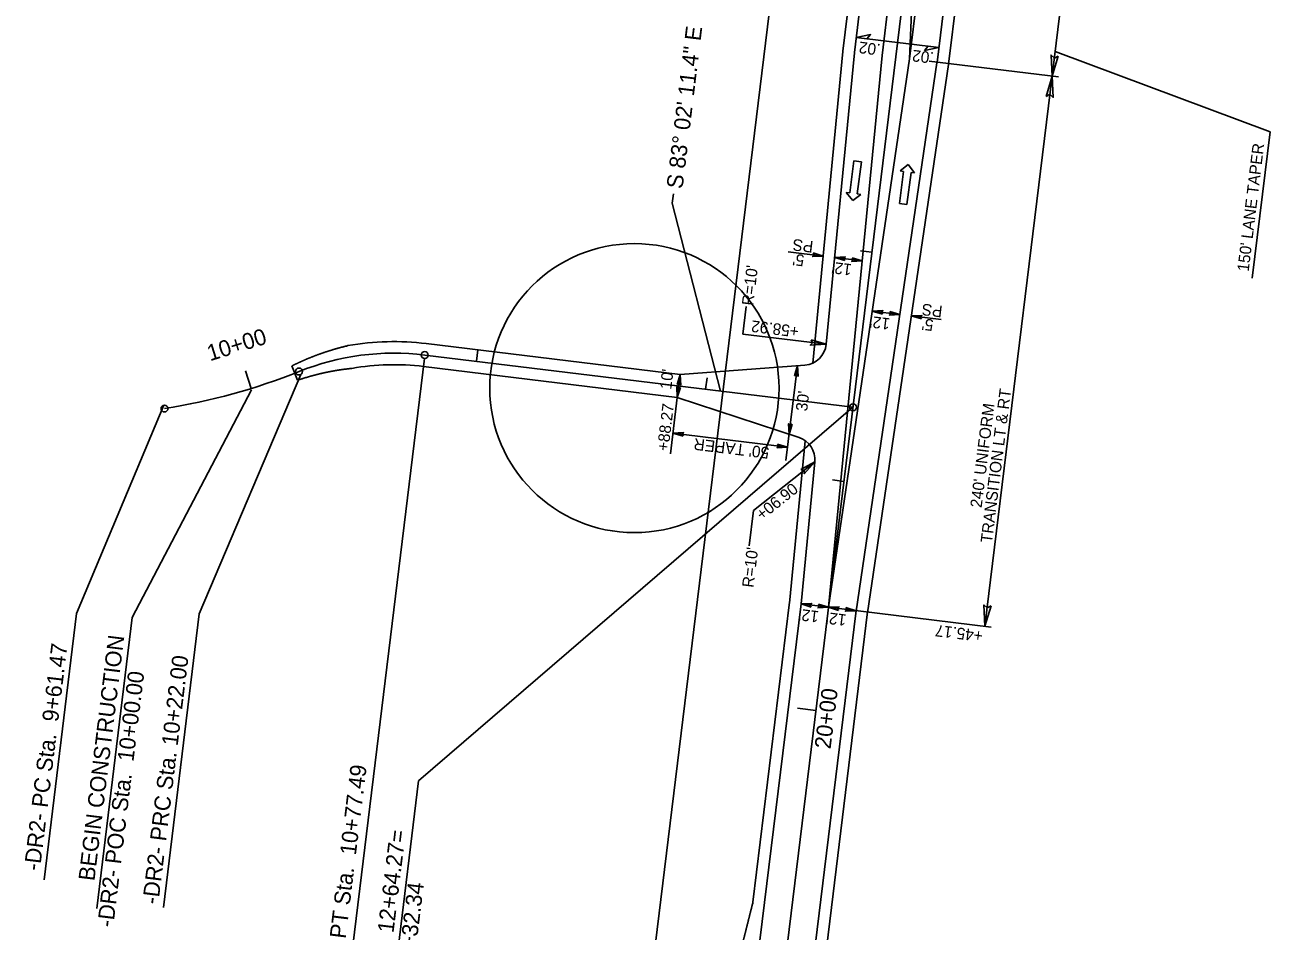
# Model space of a CAD drawing. Extents: x 472216 to 481979, y 489069 to 507339.
# Drawn here: x 480925 to 481464, y 489992 to 490385 of the extents above; entities that cross this region are included whole.
import ezdxf

# ---------------------------------------------------------------- set-up
doc = ezdxf.new("R2010")
doc.units = 0
for name, color, linetype in [('Old_Level_12', 7, 'Continuous'), ('Prop Drainage Structure Drop Inlet Grate 2 Narrow Slots and Sag Grates 840 24 CELL', 7, 'Continuous'), ('Prop Drainage Structure Drop Inlet Grate 2 Wide Slots and Sag Grates 840 22 Label', 7, 'Continuous'), ('Prop Drainage Structure Outlet Berm Ditch 850 10 CELL', 7, 'Continuous'), ('Prop Drainage Structure Pipe CSP 15in', 7, 'Continuous'), ('Prop Drainage Structure Pipe RCP 15in Class III Label', 7, 'Continuous'), ('Prop Drainage Structure Pipe RCP 24in Class III Label', 7, 'Continuous'), ('Prop Drainage Structure Pipe Side Drain 15in Label', 7, 'Continuous'), ('Prop Erosion Embankment Toe Protection CELL', 7, 'Continuous'), ('Sheet Block Revision CELL', 7, 'Continuous'), ('Sheet North Arrow Point CELL', 7, 'Continuous'), ('Sheet PE Seal Cell', 7, 'Continuous'), ('Sheet Plan And Profile CELL', 7, 'Continuous'), ('Sheet Plot Border Outside CELL', 7, 'Continuous'), ('Sheet Profile Grid Major CELL', 7, 'Continuous'), ('Sheet Profile Grid Minor CELL', 7, 'Continuous')]:
    doc.layers.add(name, color=color, linetype=linetype)

msp = doc.modelspace()

# ---------------------------------------------------------------- linework, layer by layer
at = {"layer": 'Old_Level_12'}
for p, q in [((481205.29, 490311.94), (481204.8, 490307.91)), ((481204.8, 490307.91), (481225.7, 490226.41)), ((481097.51, 490240.55), (481063.04, 489958.3)), ((481044.05, 490233.59), (481000.02, 490129.92)), ((481022.64, 490226.93), (480971.04, 490128.33)), ((480984.74, 490220.35), (480946.92, 490130.04)), ((481283.04, 490219.41), (481094.94, 490057.64)), ((480946.92, 490130.04), (480932.83, 490014.67)), ((481000.02, 490129.92), (480984.48, 490002.74)), ((480971.04, 490128.33), (480955.64, 490002.2)), ((481094.94, 490057.64), (481077.94, 489918.44))]:
    msp.add_line(p, q, dxfattribs=at)
for centre in [(481097.63, 490242.05), (481043.2, 490234.9), (480984.97, 490218.87), (481283.04, 490219.41)]:
    msp.add_circle(centre, 1.5, dxfattribs=at)
at = {"layer": 'Prop Drainage Structure Drop Inlet Grate 2 Narrow Slots and Sag Grates 840 24 CELL'}
for points in [[(481284.47, 490379.6), (481290.67, 490380.86), (481289.06, 490379.04)], [(481320.2, 490375.24), (481314.01, 490373.98), (481315.61, 490375.8)]]:
    msp.add_lwpolyline(points, close=True, dxfattribs=at)
at = {"layer": 'Prop Drainage Structure Drop Inlet Grate 2 Wide Slots and Sag Grates 840 22 Label'}
msp.add_line((481284.47, 490379.6), (481320.2, 490375.24), dxfattribs=at)
at = {"layer": 'Prop Drainage Structure Outlet Berm Ditch 850 10 CELL'}
for points in [[(481371.93, 490371.58), (481369.27, 490362.84), (481368.81, 490372.02), (481370.25, 490370.68)], [(481366.61, 490354.1), (481369.27, 490362.84), (481369.73, 490353.66), (481368.29, 490355)], [(481265.8, 490286.25), (481270.17, 490284.93), (481265.58, 490284.69), (481266.25, 490285.41)], [(481279.5, 490283.01), (481275.13, 490284.33), (481279.72, 490284.57), (481279.05, 490283.85)], [(481282.67, 490284.19), (481287.04, 490282.87), (481282.45, 490282.63), (481283.12, 490283.35)], [(481295.76, 490259.73), (481291.39, 490261.04), (481295.97, 490261.29), (481295.31, 490260.56)], [(481298.92, 490260.9), (481303.3, 490259.59), (481298.71, 490259.34), (481299.38, 490260.07)], [(481312.63, 490257.67), (481308.26, 490258.98), (481312.85, 490259.23), (481312.18, 490258.5)], [(481264.86, 490248.62), (481271.44, 490246.7), (481264.56, 490246.28), (481265.55, 490247.37)], [(481257.73, 490233.07), (481259.05, 490237.45), (481259.29, 490232.86), (481258.57, 490233.53)], [(481206.89, 490229.21), (481208.2, 490233.58), (481208.45, 490228.99), (481207.73, 490229.66)], [(481208.31, 490228.03), (481206.99, 490223.66), (481206.75, 490228.25), (481207.47, 490227.58)], [(481256.73, 490212.04), (481255.41, 490207.67), (481255.17, 490212.26), (481255.89, 490211.59)], [(481209.48, 490206.9), (481205.11, 490208.21), (481209.7, 490208.46), (481209.03, 490207.74)], [(481250.36, 490203.47), (481254.74, 490202.15), (481250.15, 490201.91), (481250.82, 490202.63)], [(481260.5, 490192.5), (481266.51, 490195.8), (481261.95, 490190.63), (481261.87, 490192.1)], [(481264.91, 490132.88), (481260.54, 490134.2), (481265.13, 490134.44), (481264.46, 490133.72)], [(481268.08, 490134.06), (481272.45, 490132.74), (481267.87, 490132.5), (481268.53, 490133.22)], [(481276.83, 490131.43), (481272.45, 490132.74), (481277.04, 490132.99), (481276.37, 490132.27)], [(481279.99, 490132.61), (481284.37, 490131.29), (481279.78, 490131.05), (481280.44, 490131.77)], [(481342.83, 490133.35), (481340.17, 490124.61), (481339.71, 490133.79), (481341.15, 490132.45)]]:
    msp.add_lwpolyline(points, close=True, dxfattribs=at)
at = {"layer": 'Prop Drainage Structure Pipe RCP 15in Class III Label'}
for p, q in [((481295.61, 490371.84), (481338.04, 490719.26)), ((481307.52, 490370.38), (481349.96, 490717.8)), ((481313.8, 490520.73), (481295.61, 490371.84)), ((481307.52, 490370.38), (481313.8, 490520.73)), ((481272.47, 490132.88), (481295.61, 490371.84)), ((481295.61, 490371.84), (481272.47, 490132.88)), ((481272.47, 490132.88), (481295.61, 490371.84)), ((481307.52, 490370.38), (481272.47, 490132.88)), ((481272.47, 490132.88), (481307.52, 490370.38))]:
    msp.add_line(p, q, dxfattribs=at)
at = {"layer": 'Prop Drainage Structure Pipe RCP 24in Class III Label'}
for p, q in [((481283.68, 490373.14), (481322.5, 490690.93)), ((481319.42, 490368.78), (481359.1, 490693.69)), ((481271.44, 490246.7), (481283.67, 490373)), ((481319.39, 490368.63), (481284.34, 490131.13)), ((481098.3, 490247.01), (481208.2, 490233.58)), ((481208.2, 490233.58), (481262.24, 490237.69)), ((481040.08, 490237.36), (481042.54, 490231.12)), ((481097.09, 490237.08), (481206.99, 490223.66)), ((481206.99, 490223.66), (481259.69, 490206.26)), ((481260.54, 490134.19), (481266.51, 490195.8)), ((481188.26, 489542.39), (481260.54, 490134.19)), ((481255.86, 489897.92), (481284.38, 490131.43))]:
    msp.add_line(p, q, dxfattribs=at)
for centre, radius, start, end in [((481084.36, 490132.85), 115, 83.0365, 99.9886), ((481261.48, 490247.66), 10, 274.3464, 354.4686), ((481084.36, 490132.85), 105, 83.0365, 99.9886), ((481256.55, 490196.76), 10, 354.4686, 71.7266)]:
    msp.add_arc(centre, radius, start, end, dxfattribs=at)
for points in [[(481040.08, 490237.36), (481040.37, 490237.49), (481040.67, 490237.63), (481040.98, 490237.78), (481041.28, 490237.92), (481041.59, 490238.07), (481041.9, 490238.21), (481042.2, 490238.36), (481042.52, 490238.51), (481042.84, 490238.65), (481043.15, 490238.8), (481043.47, 490238.95), (481043.79, 490239.09), (481044.11, 490239.23), (481044.43, 490239.38), (481044.75, 490239.52), (481045.07, 490239.66), (481045.39, 490239.8), (481045.71, 490239.94), (481046.04, 490240.07), (481046.36, 490240.21), (481046.68, 490240.35), (481047, 490240.48), (481047.33, 490240.62), (481047.65, 490240.75), (481047.98, 490240.88), (481048.3, 490241.01), (481048.63, 490241.14), (481048.96, 490241.27), (481049.28, 490241.4), (481049.61, 490241.52), (481049.94, 490241.65), (481050.27, 490241.78), (481050.59, 490241.9), (481050.92, 490242.02), (481051.25, 490242.14), (481051.58, 490242.27), (481051.91, 490242.39), (481052.24, 490242.5), (481052.57, 490242.62), (481052.91, 490242.74), (481053.24, 490242.86), (481053.57, 490242.97), (481053.9, 490243.08), (481054.24, 490243.2), (481054.57, 490243.31), (481054.9, 490243.42), (481055.24, 490243.53), (481055.57, 490243.64), (481055.91, 490243.75), (481056.24, 490243.85), (481056.58, 490243.96), (481056.92, 490244.06), (481057.25, 490244.17), (481057.59, 490244.27), (481057.93, 490244.37), (481058.27, 490244.47), (481058.6, 490244.57), (481058.94, 490244.67), (481059.28, 490244.77), (481059.62, 490244.87), (481059.96, 490244.96), (481060.3, 490245.06), (481060.64, 490245.15), (481060.98, 490245.24), (481061.32, 490245.33), (481061.67, 490245.43), (481062.01, 490245.51), (481062.35, 490245.6), (481062.69, 490245.69), (481063.03, 490245.78), (481063.38, 490245.86), (481063.72, 490245.95), (481064.41, 490246.11)], [(481042.54, 490231.12), (481042.87, 490231.23), (481043.19, 490231.33), (481043.52, 490231.44), (481043.84, 490231.54), (481044.16, 490231.64), (481044.48, 490231.75), (481044.8, 490231.85), (481045.12, 490231.95), (481045.43, 490232.05), (481045.74, 490232.14), (481046.06, 490232.24), (481046.37, 490232.33), (481046.69, 490232.43), (481047, 490232.52), (481047.32, 490232.61), (481047.63, 490232.7), (481047.94, 490232.79), (481048.26, 490232.88), (481048.58, 490232.97), (481048.89, 490233.06), (481049.21, 490233.14), (481049.52, 490233.23), (481049.84, 490233.31), (481050.16, 490233.39), (481050.47, 490233.47), (481050.79, 490233.56), (481051.11, 490233.64), (481051.42, 490233.71), (481051.74, 490233.79), (481052.06, 490233.87), (481052.38, 490233.95), (481052.69, 490234.02), (481053.01, 490234.09), (481053.33, 490234.17), (481053.65, 490234.24), (481053.97, 490234.31), (481054.28, 490234.38), (481054.6, 490234.45), (481054.92, 490234.52), (481055.24, 490234.58), (481055.56, 490234.65), (481055.88, 490234.71), (481056.2, 490234.78), (481056.52, 490234.84), (481056.84, 490234.9), (481057.16, 490234.96), (481057.48, 490235.02), (481057.8, 490235.08), (481058.12, 490235.14), (481058.44, 490235.2), (481058.76, 490235.25), (481059.08, 490235.31), (481059.4, 490235.36), (481059.72, 490235.42), (481060.04, 490235.47), (481060.36, 490235.52), (481060.68, 490235.57), (481061, 490235.62), (481061.32, 490235.66), (481061.64, 490235.71), (481061.96, 490235.76), (481062.29, 490235.8), (481062.61, 490235.85), (481062.93, 490235.89), (481063.25, 490235.93), (481063.57, 490235.97), (481063.89, 490236.01), (481064.21, 490236.05), (481064.54, 490236.09), (481064.86, 490236.13), (481065.18, 490236.16), (481065.5, 490236.2), (481066.14, 490236.26)]]:
    msp.add_spline(points, degree=3, dxfattribs=at)
at = {"layer": 'Prop Drainage Structure Pipe Side Drain 15in Label'}
for p, q in [((481281.64, 490312.28), (481283.43, 490326.16)), ((481283.43, 490326.16), (481286.7, 490325.74)), ((481286.7, 490325.74), (481284.91, 490311.85)), ((481303.43, 490321.8), (481306.9, 490324.53)), ((481306.9, 490324.53), (481309.67, 490321)), ((481303.12, 490307.73), (481304.91, 490321.61)), ((481304.91, 490321.61), (481303.43, 490321.8)), ((481308.19, 490321.19), (481306.4, 490307.3)), ((481309.67, 490321), (481308.19, 490321.19)), ((481282.92, 490308.93), (481280.15, 490312.47)), ((481280.15, 490312.47), (481281.64, 490312.28)), ((481286.4, 490311.66), (481282.92, 490308.93)), ((481284.91, 490311.85), (481286.4, 490311.66)), ((481306.4, 490307.3), (481303.12, 490307.73))]:
    msp.add_line(p, q, dxfattribs=at)
at = {"layer": 'Prop Erosion Embankment Toe Protection CELL'}
for p, q in [((481278.71, 490373.68), (481319.54, 490708)), ((481324.37, 490368.11), (481364.05, 490692.98)), ((481265.62, 490238.55), (481278.69, 490373.48)), ((481324.34, 490367.9), (481289.29, 490130.4)), ((481255.55, 490134.52), (481262.37, 490204.9)), ((481239.72, 490004.99), (481255.6, 490134.94)), ((481259.77, 489888.71), (481289.34, 490130.82))]:
    msp.add_line(p, q, dxfattribs=at)
msp.add_spline([(481231.87, 489973.71), (481231.98, 489974.13), (481232.09, 489974.55), (481232.19, 489974.97), (481232.3, 489975.4), (481232.4, 489975.82), (481232.51, 489976.24), (481232.62, 489976.66), (481232.72, 489977.09), (481232.83, 489977.51), (481232.93, 489977.93), (481233.04, 489978.36), (481233.15, 489978.78), (481233.25, 489979.2), (481233.36, 489979.62), (481233.46, 489980.05), (481233.57, 489980.47), (481233.68, 489980.89), (481233.78, 489981.31), (481233.89, 489981.74), (481233.99, 489982.16), (481234.1, 489982.58), (481234.21, 489983.01), (481234.31, 489983.43), (481234.42, 489983.85), (481234.52, 489984.27), (481234.63, 489984.7), (481234.74, 489985.12), (481234.84, 489985.54), (481234.95, 489985.96), (481235.06, 489986.39), (481235.16, 489986.81), (481235.27, 489987.23), (481235.37, 489987.65), (481235.48, 489988.08), (481235.59, 489988.5), (481235.69, 489988.92), (481235.8, 489989.35), (481235.9, 489989.77), (481236.01, 489990.19), (481236.12, 489990.61), (481236.22, 489991.04), (481236.33, 489991.46), (481236.43, 489991.88), (481236.54, 489992.3), (481236.65, 489992.73), (481236.75, 489993.15), (481236.86, 489993.57), (481236.96, 489994), (481237.07, 489994.42), (481237.18, 489994.84), (481237.28, 489995.26), (481237.39, 489995.69), (481237.5, 489996.11), (481237.6, 489996.53), (481237.71, 489996.95), (481237.81, 489997.38), (481237.92, 489997.8), (481238.03, 489998.22), (481238.13, 489998.64), (481238.24, 489999.07), (481238.34, 489999.49), (481238.45, 489999.91), (481238.56, 490000.34), (481238.66, 490000.76), (481238.77, 490001.18), (481238.87, 490001.6), (481238.98, 490002.03), (481239.09, 490002.45), (481239.19, 490002.87), (481239.3, 490003.29), (481239.4, 490003.72), (481239.51, 490004.14), (481239.72, 490004.99)], degree=3, dxfattribs=at)
at = {"layer": 'Sheet Block Revision CELL'}
for p, q in [((481340.17, 490124.61), (481411.7, 490710.26)), ((481463.61, 490338.68), (481370.58, 490373.61)), ((481371.97, 490362.51), (481315.97, 490369.35)), ((481455.87, 490275.37), (481463.61, 490338.68)), ((481270.17, 490284.93), (481254.92, 490286.8)), ((481287.05, 490282.88), (481275.13, 490284.33)), ((481235.37, 490251.1), (481236.83, 490263.07)), ((481303.25, 490259.6), (481291.34, 490261.05)), ((481321.16, 490257.41), (481308.26, 490258.98)), ((481271.44, 490246.7), (481235.37, 490251.1)), ((481254.02, 490196.28), (481259.05, 490237.45)), ((481206.99, 490223.66), (481208.2, 490233.58)), ((481206.99, 490223.66), (481204.01, 490199.24)), ((481254.74, 490202.15), (481205.11, 490208.21)), ((481266.51, 490195.8), (481240.01, 490174.68)), ((481240.01, 490174.68), (481238.14, 490159.38)), ((481342.86, 490124.15), (481260.55, 490134.2))]:
    msp.add_line(p, q, dxfattribs=at)
at = {"layer": 'Sheet North Arrow Point CELL'}
for p, q in [((481200.24, 489541.46), (481402.27, 491195.58)), ((481184.4, 489879.88), (481322.35, 491009.3)), ((481097.63, 490242.05), (481283.04, 490219.41))]:
    msp.add_line(p, q, dxfattribs=at)
for centre, radius, start, end in [((481084.3, 490132.86), 110, 83.0365, 111.9362), ((480944.21, 490480.71), 265, 278.8486, 291.9362)]:
    msp.add_arc(centre, radius, start, end, dxfattribs=at)
at = {"layer": 'Sheet PE Seal Cell'}
for p, q in [((481291.24, 490286.57), (481286.28, 490287.17)), ((481119.98, 490239.32), (481120.59, 490244.28)), ((481219.24, 490227.2), (481219.85, 490232.16)), ((481279.12, 490187.3), (481274.15, 490187.91))]:
    msp.add_line(p, q, dxfattribs=at)
at = {"layer": 'Sheet Plot Border Outside CELL'}
msp.add_circle((481188.4, 490227.71), 62.61, dxfattribs=at)
at = {"layer": 'Sheet Profile Grid Minor CELL'}
for p, q in [((481022.48, 490227.53), (481020.11, 490235.18)), ((481266.99, 490088.04), (481259.05, 490089.01))]:
    msp.add_line(p, q, dxfattribs=at)

# ---------------------------------------------------------------- texts
at = {"layer": 'Old_Level_12'}
for s, p in [('BEGIN CONSTRUCTION', (480954.63, 490013.96)), ('-DR2- PC Sta.  9+61.47', (480931.02, 490018.34)), ('-DR2- PRC Sta. 10+22.00', (480982.27, 490003.82)), ('-DR2- POC Sta.  10+00.00', (480962.75, 489993.87)), ('-DR2- PT Sta.  10+77.49', (481060.05, 489961.6)), ('-DR2- POT Sta.  12+64.27=', (481075.46, 489920.7)), ('-L- POT Sta. 21+32.34', (481085.89, 489919.43))]:
    msp.add_text(s, height=7, rotation=83.0365, dxfattribs=at).set_placement(p)
at = {"layer": 'Prop Drainage Structure Drop Inlet Grate 2 Narrow Slots and Sag Grates 840 24 CELL'}
for p in [(481295.17, 490376.73), (481318.24, 490373.17)]:
    msp.add_text('.02', height=5, rotation=173.0359, dxfattribs=at).set_placement(p)
at = {"layer": 'Prop Drainage Structure Pipe CSP 15in'}
for s, rotation, p in [("150' LANE TAPER", 83.0365, (481454.32, 490278)), ('PS', 173.0365, (481266.09, 490291.3)), ("R=10'", 83.0365, (481239.84, 490263.26)), ("5'", 173.0365, (481262.19, 490285.39)), ("12'", 173.0365, (481282.75, 490281.38)), ('PS', 173.0365, (481322.02, 490263.28)), ('+58.92', 173.0365, (481259.83, 490254.57)), ("12'", 173.0365, (481299.28, 490257.91)), ("5'", 173.0365, (481318.12, 490257.37)), ("10'", 83.0365, (481204.34, 490226.95)), ('TRANSITION LT & RT', 82.8641, (481343.18, 490160.41)), ("30'", 83.0365, (481263.17, 490217.49)), ('+88.27', 83.0365, (481203.08, 490200.22)), ("240' UNIFORM ", 82.8641, (481338.71, 490175.68)), ("50' TAPER", 173.0365, (481247, 490202.03)), ('+06.90', 38.5464, (481243.62, 490170.24)), ("R=10'", 83.0365, (481239.94, 490141.09)), ("12'", 173.0365, (481268.49, 490131.04)), ("12'", 173.0365, (481280.4, 490129.59)), ('+45.17', 173.0388, (481339.47, 490122.7))]:
    msp.add_text(s, height=5, rotation=rotation, dxfattribs=at).set_placement(p)
at = {"layer": 'Sheet Plan And Profile CELL'}
msp.add_text('S 83%%d 02\' 11.4" E', height=7, rotation=83.0365, dxfattribs=at).set_placement((481209.22, 490313.8))
at = {"layer": 'Sheet Profile Grid Major CELL'}
for s, rotation, p in [('10+00', 17.179, (481004.68, 490239.34)), ('20+00', 83.0365, (481273.32, 490071.13))]:
    msp.add_text(s, height=7, rotation=rotation, dxfattribs=at).set_placement(p)

doc.saveas('drawing.dxf')
